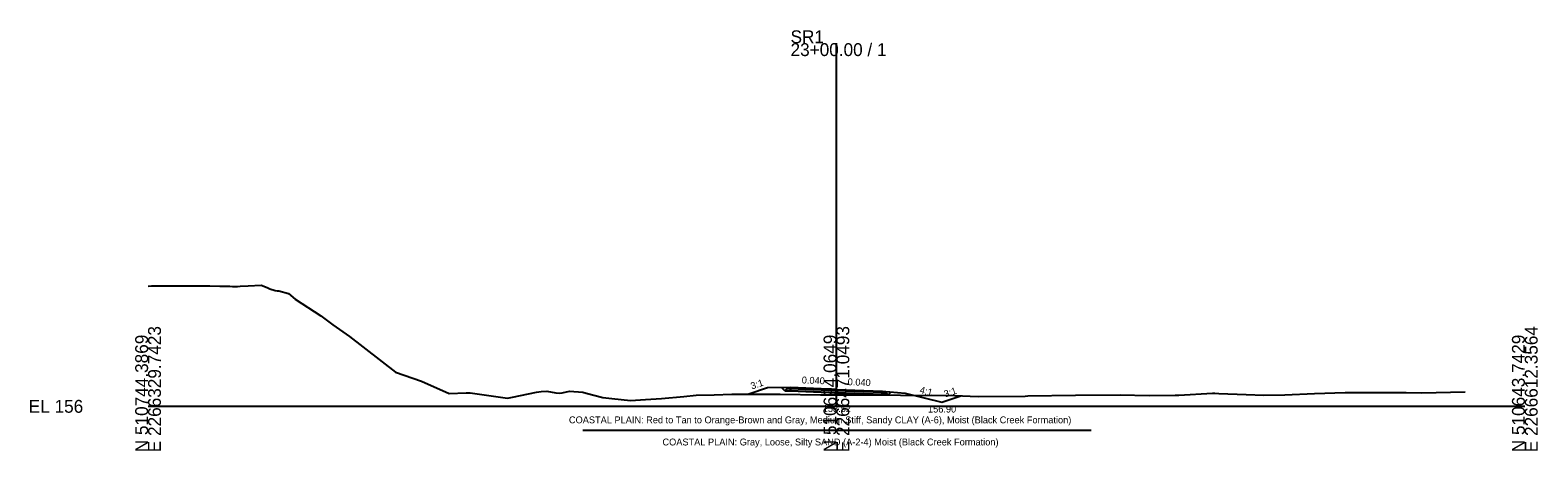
# Model space of a CAD drawing. Extents: x -1079 to 303, y -11 to 4017.
# Drawn here: x -25.7 to 302.8, y 1990.3 to 2081.9 of the extents above; entities that cross this region are included whole.
import ezdxf

# ---------------------------------------------------------------- set-up
doc = ezdxf.new("R2010")
doc.units = 0
for name, color, linetype in [('Default', 7, 'Continuous'), ('Exist Cross Section Cell', 7, 'Continuous'), ('Exist XS Center Line Elevation Label', 7, 'Continuous'), ('Exist XS Ground Line', 7, 'Continuous'), ('Prop CMT Pvmt Course 1', 7, 'Continuous'), ('Prop CMT Pvmt Course 2', 7, 'Continuous'), ('Prop CMT Pvmt Course 3', 7, 'Continuous'), ('Prop CMT Pvmt Surface', 7, 'Continuous'), ('Prop CMT Pvmt Surface Shoulder', 7, 'Continuous'), ('Prop CMT Shld Paved Course 1', 7, 'Continuous'), ('Prop CMT Shld Paved Course 2', 7, 'Continuous'), ('Prop CMT Shld Paved Course 3', 7, 'Continuous'), ('Prop CMT Slope Grass', 7, 'Continuous'), ('Prop CMT Subgrade Earthwork', 7, 'Continuous'), ('Prop Road Sect_ Material - Contact (General - Minor)', 7, 'Continuous'), ('Prop Road Sect_ Material - Tx (Composite Desc)', 7, 'Continuous'), ('Prop XS Ditch Standard Text', 7, 'Continuous'), ('Prop XS SE Text', 7, 'Continuous'), ('Prop XS Side Slope Text', 7, 'Continuous')]:
    doc.layers.add(name, color=color, linetype=linetype)

msp = doc.modelspace()

# ---------------------------------------------------------------- linework, layer by layer
at = {"layer": 'Exist Cross Section Cell'}
for p, q in [((150, 2000), (150, 2079.09)), ((0, 2000), (150, 2000)), ((150, 2000), (300, 2000))]:
    msp.add_line(p, q, dxfattribs=at)
at = {"layer": 'Exist XS Ground Line'}
msp.add_lwpolyline([(0, 2026.2), (0.72, 2026.21), (1.78, 2026.22), (2.14, 2026.23), (2.9, 2026.23), (4.78, 2026.25), (7.06, 2026.27), (7.49, 2026.28), (7.85, 2026.28), (8.87, 2026.27), (10.07, 2026.26), (11.53, 2026.26), (12.71, 2026.25), (13.49, 2026.23), (15.64, 2026.19), (17.79, 2026.14), (18.39, 2026.12), (19.52, 2026.13), (20.07, 2026.14), (21.81, 2026.26), (24.67, 2026.36), (25.97, 2025.88), (26.53, 2025.57), (27.7, 2025.22), (28.14, 2025.17), (28.47, 2025.14), (30.62, 2024.55), (32.03, 2023.33), (37.68, 2019.68), (40.27, 2017.75), (43.92, 2015.24), (53.95, 2007.43), (59.6, 2005.5), (65.58, 2002.78), (69.33, 2002.93), (70.19, 2002.97), (70.66, 2002.89), (78.31, 2001.75), (79.39, 2001.98), (84.61, 2003.08), (85.69, 2003.21), (86.86, 2003.31), (88.85, 2002.96), (89.61, 2002.85), (90.21, 2002.96), (91.86, 2003.33), (94.74, 2003.09), (95.45, 2002.89), (99.09, 2001.89), (101.06, 2001.69), (105.13, 2001.27), (108.43, 2001.47), (111.89, 2001.68), (116.73, 2002.15), (119.46, 2002.42), (123.34, 2002.53), (127.18, 2002.64), (129.15, 2002.63), (137.73, 2002.65), (146.56, 2002.54), (148.36, 2002.52), (150, 2002.52), (157.62, 2002.51), (160.04, 2002.51), (167.88, 2002.37), (170.63, 2002.41), (175.72, 2002.33), (180.85, 2002.14), (191.09, 2002.24), (191.67, 2002.25), (202.08, 2002.4), (211.86, 2002.52), (218.18, 2002.34), (223.81, 2002.4), (224.59, 2002.45), (231.97, 2002.87), (232.44, 2002.85), (233.35, 2002.81), (239.3, 2002.57), (243.13, 2002.43), (247.72, 2002.54), (254.15, 2002.8), (260.83, 2003.03), (265.78, 2002.98), (274.12, 2003.03), (277.48, 2002.97), (287.02, 2003.19)], dxfattribs=at)
at = {"layer": 'Prop CMT Pvmt Course 1'}
for points in [[(150, 2003.7), (140, 2004.1)], [(140, 2004.1), (140, 2003.85)], [(140, 2003.85), (150, 2003.45)], [(150, 2003.45), (150, 2003.7)], [(150, 2003.7), (160, 2003.3)], [(150, 2003.45), (150, 2003.7)], [(160, 2003.05), (150, 2003.45)], [(160, 2003.3), (160, 2003.05)]]:
    msp.add_lwpolyline(points, dxfattribs=at)
msp.add_lwpolyline([(150, 2003.45), (150, 2003.57), (150, 2003.57), (150, 2003.45)], close=True, dxfattribs=at)
msp.add_lwpolyline([(150, 2003.45), (150, 2003.57), (150, 2003.57), (150, 2003.45)], close=True, dxfattribs=at)
at = {"layer": 'Prop CMT Pvmt Course 2'}
for points in [[(140, 2003.85), (150, 2003.45)], [(150, 2003.45), (140, 2003.85)], [(140, 2003.85), (140, 2003.85)], [(150, 2003.45), (150, 2003.45)], [(160, 2003.05), (150, 2003.45)], [(150, 2003.45), (150, 2003.45)], [(150, 2003.45), (160, 2003.05)], [(160, 2003.05), (160, 2003.05)]]:
    msp.add_lwpolyline(points, dxfattribs=at)
at = {"layer": 'Prop CMT Pvmt Course 3'}
for points in [[(150, 2003.45), (140, 2003.85)], [(140, 2003.85), (140, 2003.35)], [(140, 2003.35), (150, 2002.95)], [(150, 2002.95), (150, 2003.45)], [(150, 2003.45), (160, 2003.05)], [(150, 2002.95), (150, 2003.45)], [(160, 2002.55), (150, 2002.95)], [(160, 2003.05), (160, 2002.55)]]:
    msp.add_lwpolyline(points, dxfattribs=at)
at = {"layer": 'Prop CMT Pvmt Surface'}
for q in [(140, 2004.1), (160, 2003.3)]:
    msp.add_line((150, 2003.7), q, dxfattribs=at)
at = {"layer": 'Prop CMT Pvmt Surface Shoulder'}
for p, q in [((140, 2004.1), (140, 2004.1)), ((160, 2003.3), (160, 2003.3))]:
    msp.add_line(p, q, dxfattribs=at)
at = {"layer": 'Prop CMT Shld Paved Course 1'}
for points in [[(140, 2004.1), (140, 2004.1), (139.76, 2003.86)], [(140, 2003.85), (140, 2004.1)], [(139.76, 2003.86), (140, 2003.85)], [(160, 2003.3), (160, 2003.3), (160.26, 2003.04)], [(160, 2003.05), (160, 2003.3)], [(160.26, 2003.04), (160, 2003.05)]]:
    msp.add_lwpolyline(points, dxfattribs=at)
at = {"layer": 'Prop CMT Shld Paved Course 2'}
for points in [[(140, 2003.85), (139.76, 2003.86)], [(139.76, 2003.86), (139.76, 2003.86)], [(139.76, 2003.86), (140, 2003.85)], [(140, 2003.85), (140, 2003.85)], [(160, 2003.05), (160.26, 2003.04)], [(160.26, 2003.04), (160, 2003.05)], [(160, 2003.05), (160, 2003.05)], [(160.26, 2003.04), (160.26, 2003.04)]]:
    msp.add_lwpolyline(points, dxfattribs=at)
at = {"layer": 'Prop CMT Shld Paved Course 3'}
for points in [[(140, 2003.85), (139.76, 2003.86), (139.26, 2003.88), (138.78, 2003.4)], [(138.78, 2003.4), (140, 2003.35)], [(140, 2003.35), (140, 2003.85)], [(160, 2003.05), (160.26, 2003.04), (160.76, 2003.02), (161.28, 2002.5)], [(160, 2002.55), (160, 2003.05)], [(161.28, 2002.5), (160, 2002.55)]]:
    msp.add_lwpolyline(points, dxfattribs=at)
at = {"layer": 'Prop CMT Slope Grass'}
for p, q in [((140, 2004.1), (135, 2004)), ((135, 2004), (130.92, 2002.64)), ((160, 2003.3), (165, 2002.9)), ((165, 2002.9), (173, 2000.9)), ((173, 2000.9), (177.13, 2002.28))]:
    msp.add_line(p, q, dxfattribs=at)
at = {"layer": 'Prop CMT Subgrade Earthwork'}
for points in [[(138.78, 2003.4), (138.11, 2004.06)], [(140, 2003.35), (138.78, 2003.4)], [(150, 2002.95), (140, 2003.35)], [(150, 2002.95), (160, 2002.55)], [(160, 2002.55), (161.28, 2002.5)], [(161.28, 2002.5), (161.93, 2003.14)]]:
    msp.add_lwpolyline(points, dxfattribs=at)
at = {"layer": 'Prop Road Sect_ Material - Contact (General - Minor)'}
msp.add_line((205.49, 1994.72), (94.73, 1994.72), dxfattribs=at)

# ---------------------------------------------------------------- texts
at = {"layer": 'Default'}
msp.add_text('-', height=0.0001, dxfattribs=at).set_placement((0, 2000))
at = {"layer": 'Exist Cross Section Cell'}
for s, p in [('SR1', (140, 2079.09)), ('23+00.00 / 1', (140, 2076.29)), ('EL 156', (-26, 1998.6))]:
    msp.add_text(s, height=2.8, dxfattribs=at).set_placement(p)
for s, p in [('E 2266329.7423', (2.8, 1990)), ('E 2266471.0493', (152.8, 1990)), ('E 2266612.3564', (302.8, 1990)), ('N 510744.3869', (0, 1990)), ('N 510694.0649', (150, 1990)), ('N 510643.7429', (300, 1990))]:
    msp.add_text(s, height=2.8, rotation=90, dxfattribs=at).set_placement(p)
at = {"layer": 'Exist XS Center Line Elevation Label'}
msp.add_text('158.52', height=1.5, dxfattribs=at).set_placement((147.02, 1998.77))
at = {"layer": 'Prop Road Sect_ Material - Tx (Composite Desc)'}
for s, p in [('COASTAL PLAIN: Red to Tan to Orange-Brown and Gray, Medium Stiff, Sandy CLAY (A-6), Moist (Black Creek Formation)', (91.71, 1996.3)), ('COASTAL PLAIN: Gray, Loose, Silty SAND (A-2-4) Moist (Black Creek Formation)', (112.09, 1991.48))]:
    msp.add_text(s, height=1.5, dxfattribs=at).set_placement(p)
at = {"layer": 'Prop XS Ditch Standard Text'}
msp.add_text('156.90', height=1.5, dxfattribs=at).set_placement((169.96, 1998.65))
at = {"layer": 'Prop XS SE Text'}
for p in [(142.42, 2005), (152.42, 2004.6)]:
    msp.add_text('0.040', height=1.5, rotation=357.7094, dxfattribs=at).set_placement(p)
at = {"layer": 'Prop XS Side Slope Text'}
for s, rotation, p in [('3:1', 18.4332, (131.59, 2003.65)), ('4:1', 345.9638, (168.03, 2002.91)), ('3:1', 18.4332, (173.7, 2001.92))]:
    msp.add_text(s, height=1.5, rotation=rotation, dxfattribs=at).set_placement(p)

doc.saveas('drawing.dxf')
